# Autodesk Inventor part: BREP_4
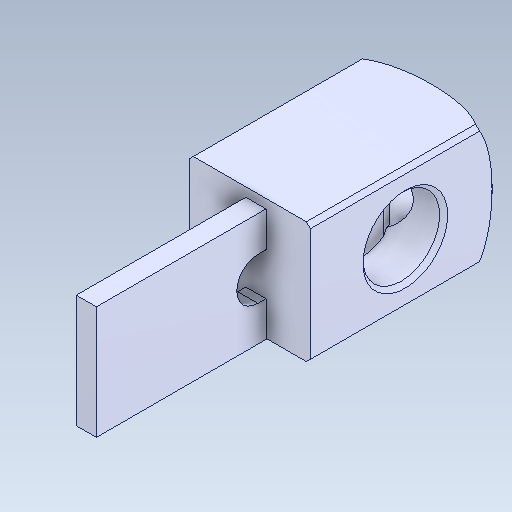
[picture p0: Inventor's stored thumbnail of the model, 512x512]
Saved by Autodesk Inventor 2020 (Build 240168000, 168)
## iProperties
Created: 2017-09
Part Number: BREP_4
Material: Générique
Document SubType Name: Modeling
Designer: bruno
Density: 1 g/cm^3
Appearance: Par défaut
Author: bruno
Sending System: SolidWorks 2016
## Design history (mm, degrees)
feature "Importée1"
node "Solide1"
